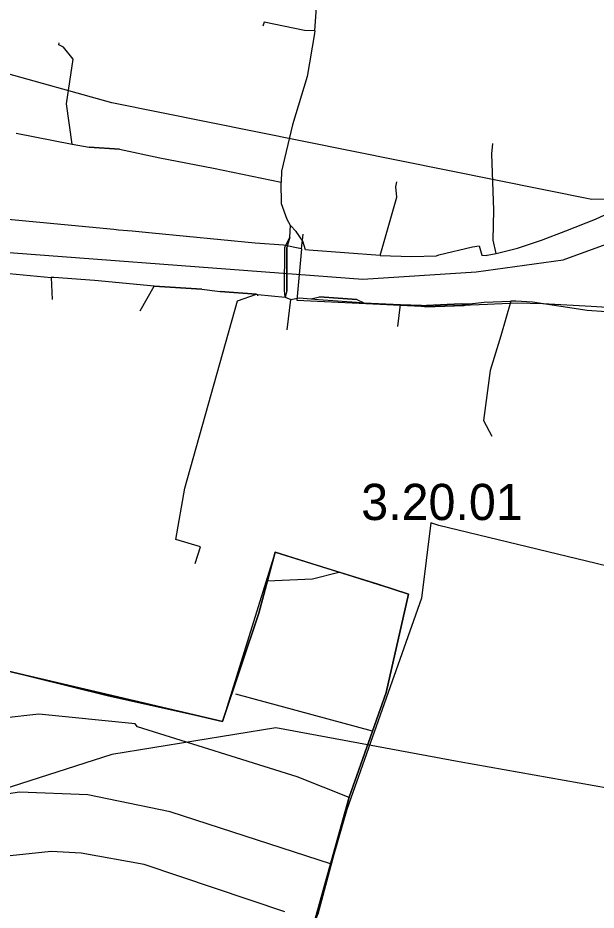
# Model space of a CAD drawing. Extents: x -662500 to -653478, y -1056827 to -1049993.
# Drawn here: x -660470.9 to -660351.1, y -1052282.8 to -1052097.9 of the extents above; entities that cross this region are included whole.
import ezdxf

# ---------------------------------------------------------------- set-up
doc = ezdxf.new("R2010")
doc.units = 0
for name, color, linetype in [('Vrstva 1', 7, 'Continuous'), ('Vrstva 20', 7, 'Continuous'), ('Vrstva 24', 7, 'Continuous'), ('Vrstva 45', 7, 'Continuous'), ('Vrstva 48', 7, 'Continuous'), ('Vrstva 5', 7, 'Continuous'), ('Vrstva 6', 7, 'Continuous'), ('Vrstva 7', 7, 'Continuous')]:
    doc.layers.add(name, color=color, linetype=linetype)

msp = doc.modelspace()

# ---------------------------------------------------------------- linework, layer by layer
at = {"layer": 'Vrstva 1'}
msp.add_lwpolyline([(-660408.77, -1052283.62), (-660402.29, -1052259.33), (-660394.65, -1052237.63), (-660389.99, -1052217.3), (-660396.18, -1052215.3), (-660414.84, -1052209.49), (-660417.67, -1052208.59), (-660421.03, -1052221.2), (-660427.21, -1052239.6), (-660428.58, -1052243.68), (-660452.47, -1052238.38), (-660475.36, -1052232.69), (-660497.36, -1052226.43)], dxfattribs=at)
at = {"layer": 'Vrstva 20'}
msp.add_lwpolyline([(-660611.17, -1052274.32), (-660487.99, -1052312.15), (-660486.82, -1052314.01), (-660462.36, -1052329.02), (-660459.17, -1052336.8), (-660433.93, -1052352.12), (-660408.77, -1052283.62), (-660402.29, -1052259.33), (-660394.65, -1052237.63), (-660389.99, -1052217.3), (-660417.67, -1052208.59), (-660428.58, -1052243.68), (-660475.36, -1052232.69), (-660499.48, -1052225.45), (-660495.07, -1052211.29), (-660578.14, -1052190.03), (-660563.85, -1052144.19), (-660586.5, -1052144.05), (-660704.06, -1052109.9), (-660743.35, -1052235.04)], close=True, dxfattribs=at)
at = {"layer": 'Vrstva 24'}
for points in [[(-660328, -1052135), (-660352, -1052135.5), (-660451.5, -1052115.5), (-660661, -1052057), (-660695, -1052042.5), (-660723, -1052024.5), (-660747.5, -1052000), (-660756.5, -1051991), (-660777.56, -1051972.71)], [(-660320.5, -1052262.5), (-660379.5, -1052252), (-660417.5, -1052245), (-660451.5, -1052250.5), (-660478, -1052259), (-660504, -1052263), (-660539, -1052261), (-660579, -1052252), (-660609, -1052240.5), (-660650.5, -1052213), (-660664.5, -1052194.5), (-660663.5, -1052181.5), (-660652.5, -1052172), (-660629.5, -1052164.5), (-660535, -1052163), (-660529, -1052158), (-660526, -1052149), (-660537.5, -1052137), (-660493, -1052145), (-660399.5, -1052152), (-660376, -1052150.5), (-660358, -1052148), (-660341.5, -1052142)]]:
    msp.add_lwpolyline(points, dxfattribs=at)
at = {"layer": 'Vrstva 45'}
for p, q in [((-660409.45, -1052100.6), (-660408.7, -1052090.8)), ((-660409.45, -1052100.6), (-660408.7, -1052090.8)), ((-660409.45, -1052100.6), (-660408.7, -1052090.8)), ((-660409.45, -1052100.6), (-660408.7, -1052090.8)), ((-660471.3, -1052121.8), (-660459.7, -1052124.03)), ((-660471.3, -1052121.8), (-660459.7, -1052124.03)), ((-660449.9, -1052125.06), (-660456.15, -1052124.67)), ((-660449.9, -1052125.06), (-660456.15, -1052124.67)), ((-660357.45, -1052142.04), (-660351.29, -1052139.56)), ((-660357.45, -1052142.04), (-660351.29, -1052139.56)), ((-660414.61, -1052143.32), (-660414.46, -1052140.93)), ((-660414.61, -1052143.32), (-660414.46, -1052140.93)), ((-660414.61, -1052143.32), (-660414.46, -1052140.93)), ((-660414.61, -1052143.32), (-660414.46, -1052140.93)), ((-660414.46, -1052140.93), (-660413.28, -1052142.15)), ((-660414.46, -1052140.93), (-660413.28, -1052142.15)), ((-660414.46, -1052140.93), (-660413.28, -1052142.15)), ((-660414.46, -1052140.93), (-660413.28, -1052142.15)), ((-660413.28, -1052142.15), (-660413.15, -1052142.16)), ((-660413.28, -1052142.15), (-660413.15, -1052142.16)), ((-660413.28, -1052142.15), (-660413.15, -1052142.16)), ((-660413.28, -1052142.15), (-660413.15, -1052142.16)), ((-660412.15, -1052145.73), (-660411.84, -1052142.72)), ((-660412.15, -1052145.73), (-660411.84, -1052142.72)), ((-660415.67, -1052154.38), (-660415.63, -1052145.48)), ((-660415.67, -1052154.38), (-660415.63, -1052145.48)), ((-660415.23, -1052154.43), (-660415.22, -1052145.47)), ((-660415.23, -1052154.43), (-660415.22, -1052145.47)), ((-660383.74, -1052147.01), (-660376.78, -1052145.3)), ((-660383.74, -1052147.01), (-660376.78, -1052145.3)), ((-660395.86, -1052147.1), (-660389.4, -1052147.3)), ((-660395.86, -1052147.1), (-660389.4, -1052147.3)), ((-660464.01, -1052151.68), (-660463.81, -1052156.27)), ((-660464.01, -1052151.68), (-660463.81, -1052156.27)), ((-660455.08, -1052152.33), (-660463.52, -1052151.69)), ((-660455.08, -1052152.33), (-660463.52, -1052151.69)), ((-660445.59, -1052158.59), (-660442.67, -1052153.44)), ((-660445.59, -1052158.59), (-660442.67, -1052153.44)), ((-660432.84, -1052154.12), (-660442.67, -1052153.44)), ((-660432.84, -1052154.12), (-660442.67, -1052153.44)), ((-660421.53, -1052155.16), (-660429.05, -1052154.56)), ((-660421.53, -1052155.16), (-660429.05, -1052154.56)), ((-660421.53, -1052155.16), (-660421.22, -1052155.19)), ((-660421.53, -1052155.16), (-660421.22, -1052155.19)), ((-660421.24, -1052155.49), (-660421.22, -1052155.19)), ((-660421.24, -1052155.49), (-660421.22, -1052155.19)), ((-660421.22, -1052155.19), (-660415.55, -1052155.73)), ((-660421.22, -1052155.19), (-660415.55, -1052155.73)), ((-660415.55, -1052155.73), (-660414.38, -1052156.21)), ((-660415.55, -1052155.73), (-660414.38, -1052156.21)), ((-660415.55, -1052155.73), (-660414.38, -1052156.21)), ((-660415.55, -1052155.73), (-660414.38, -1052156.21)), ((-660415.16, -1052162.49), (-660414.38, -1052156.21)), ((-660415.16, -1052162.49), (-660414.38, -1052156.21)), ((-660408.67, -1052156.23), (-660400.79, -1052156.82)), ((-660408.67, -1052156.23), (-660400.79, -1052156.82)), ((-660400.73, -1052156.27), (-660408.48, -1052155.7)), ((-660400.73, -1052156.27), (-660408.48, -1052155.7)), ((-660399.25, -1052156.91), (-660391.69, -1052157.24)), ((-660399.25, -1052156.91), (-660391.69, -1052157.24)), ((-660399.25, -1052156.91), (-660391.69, -1052157.24)), ((-660399.25, -1052156.91), (-660391.69, -1052157.24)), ((-660392.21, -1052161.8), (-660391.69, -1052157.24)), ((-660392.21, -1052161.8), (-660391.69, -1052157.24)), ((-660391.69, -1052157.24), (-660387.41, -1052157.44)), ((-660391.69, -1052157.24), (-660387.41, -1052157.44)), ((-660391.69, -1052157.24), (-660387.41, -1052157.44)), ((-660391.69, -1052157.24), (-660387.41, -1052157.44)), ((-660378.45, -1052157.45), (-660386.48, -1052157.76)), ((-660378.45, -1052157.45), (-660386.48, -1052157.76)), ((-660379.12, -1052157.16), (-660386.3, -1052157.46)), ((-660379.12, -1052157.16), (-660386.3, -1052157.46)), ((-660362.2, -1052157.04), (-660352.16, -1052157.62)), ((-660362.2, -1052157.04), (-660352.16, -1052157.62))]:
    msp.add_line(p, q, dxfattribs=at)
for points in [[(-660409.45, -1052100.6), (-660411.57, -1052100.48), (-660419.94, -1052098.78), (-660420.18, -1052099.59)], [(-660409.45, -1052100.6), (-660411.57, -1052100.48), (-660419.94, -1052098.78), (-660420.18, -1052099.59)], [(-660409.45, -1052100.6), (-660409.46, -1052101.13), (-660410.98, -1052110.03), (-660414.04, -1052120.04), (-660416.32, -1052129.63), (-660416.38, -1052131.95)], [(-660409.45, -1052100.6), (-660409.46, -1052101.13), (-660410.98, -1052110.03), (-660414.04, -1052120.04), (-660416.32, -1052129.63), (-660416.38, -1052131.95)], [(-660409.45, -1052100.6), (-660409.46, -1052101.13), (-660410.98, -1052110.03), (-660414.04, -1052120.04), (-660416.32, -1052129.63), (-660416.38, -1052131.95)], [(-660409.45, -1052100.6), (-660409.46, -1052101.13), (-660410.98, -1052110.03), (-660414.04, -1052120.04), (-660416.32, -1052129.63), (-660416.38, -1052131.95)], [(-660459.7, -1052124.03), (-660460.85, -1052115.69), (-660459.5, -1052106.42), (-660461.49, -1052103.98), (-660462.47, -1052103.46), (-660462.39, -1052103.03)], [(-660459.7, -1052124.03), (-660460.85, -1052115.69), (-660459.5, -1052106.42), (-660461.49, -1052103.98), (-660462.47, -1052103.46), (-660462.39, -1052103.03)], [(-660459.7, -1052124.03), (-660456.15, -1052124.67), (-660449.9, -1052125.06), (-660441.55, -1052126.88), (-660430.39, -1052129.05), (-660416.38, -1052131.95)], [(-660459.7, -1052124.03), (-660456.15, -1052124.67), (-660449.9, -1052125.06), (-660441.55, -1052126.88), (-660430.39, -1052129.05), (-660416.38, -1052131.95)], [(-660371.84, -1052146.69), (-660372.47, -1052143.93), (-660372.32, -1052137.7), (-660372.73, -1052126.06), (-660372.52, -1052123.9)], [(-660371.84, -1052146.69), (-660372.47, -1052143.93), (-660372.32, -1052137.7), (-660372.73, -1052126.06), (-660372.52, -1052123.9)], [(-660414.46, -1052140.93), (-660415.17, -1052139.69), (-660416.3, -1052136.39), (-660416.38, -1052131.95)], [(-660414.46, -1052140.93), (-660415.17, -1052139.69), (-660416.3, -1052136.39), (-660416.38, -1052131.95)], [(-660414.46, -1052140.93), (-660415.17, -1052139.69), (-660416.3, -1052136.39), (-660416.38, -1052131.95)], [(-660414.46, -1052140.93), (-660415.17, -1052139.69), (-660416.3, -1052136.39), (-660416.38, -1052131.95)], [(-660395.86, -1052147.1), (-660392.4, -1052135.02), (-660392.66, -1052132.92), (-660392.41, -1052131.85)], [(-660395.86, -1052147.1), (-660392.4, -1052135.02), (-660392.66, -1052132.92), (-660392.41, -1052131.85)], [(-660371.84, -1052146.69), (-660367.41, -1052145.57), (-660362.45, -1052143.97), (-660357.45, -1052142.04), (-660351.29, -1052139.56), (-660343.57, -1052136.03), (-660337.69, -1052133.38)], [(-660371.84, -1052146.69), (-660367.41, -1052145.57), (-660362.45, -1052143.97), (-660357.45, -1052142.04), (-660351.29, -1052139.56), (-660343.57, -1052136.03), (-660337.69, -1052133.38)], [(-660450.08, -1052141.84), (-660451.03, -1052141.75), (-660516.13, -1052135.6)], [(-660450.08, -1052141.84), (-660451.03, -1052141.75), (-660516.13, -1052135.6)], [(-660443.11, -1052142.49), (-660447.25, -1052142.1), (-660450.08, -1052141.84)], [(-660443.11, -1052142.49), (-660447.25, -1052142.1), (-660450.08, -1052141.84)], [(-660412.15, -1052145.73), (-660415.93, -1052144.97), (-660421.76, -1052144.56), (-660443.11, -1052142.49)], [(-660412.15, -1052145.73), (-660415.93, -1052144.97), (-660421.76, -1052144.56), (-660443.11, -1052142.49)], [(-660415.55, -1052155.73), (-660415.67, -1052154.38), (-660415.63, -1052145.48), (-660414.61, -1052143.32)], [(-660415.55, -1052155.73), (-660415.67, -1052154.38), (-660415.63, -1052145.48), (-660414.61, -1052143.32)], [(-660414.61, -1052143.32), (-660415.22, -1052145.47), (-660415.23, -1052154.43), (-660415.55, -1052155.73)], [(-660414.61, -1052143.32), (-660415.22, -1052145.47), (-660415.23, -1052154.43), (-660415.55, -1052155.73)], [(-660395.86, -1052147.1), (-660410.66, -1052146.01), (-660411.32, -1052145.93), (-660411.9, -1052144.14), (-660413.28, -1052142.15)], [(-660395.86, -1052147.1), (-660410.66, -1052146.01), (-660411.32, -1052145.93), (-660411.9, -1052144.14), (-660413.28, -1052142.15)], [(-660395.86, -1052147.1), (-660389.4, -1052147.3), (-660384.24, -1052147.22), (-660383.74, -1052147.01), (-660376.78, -1052145.3), (-660375.37, -1052145.15), (-660374.79, -1052147.04), (-660373.91, -1052147.12), (-660373.75, -1052147.05), (-660371.84, -1052146.69)], [(-660395.86, -1052147.1), (-660389.4, -1052147.3), (-660384.24, -1052147.22), (-660383.74, -1052147.01), (-660376.78, -1052145.3), (-660375.37, -1052145.15), (-660374.79, -1052147.04), (-660373.91, -1052147.12), (-660373.75, -1052147.05), (-660371.84, -1052146.69)], [(-660412.15, -1052145.73), (-660413.13, -1052156.36), (-660385.96, -1052157.72), (-660373.68, -1052157.19), (-660372.23, -1052157.15)], [(-660412.15, -1052145.73), (-660413.13, -1052156.36), (-660385.96, -1052157.72), (-660373.68, -1052157.19), (-660372.23, -1052157.15)], [(-660492.67, -1052149.21), (-660484.44, -1052149.72), (-660464.01, -1052151.68)], [(-660492.67, -1052149.21), (-660484.44, -1052149.72), (-660464.01, -1052151.68)], [(-660442.67, -1052153.44), (-660455.08, -1052152.33), (-660463.52, -1052151.69), (-660464.01, -1052151.68)], [(-660442.67, -1052153.44), (-660455.08, -1052152.33), (-660463.52, -1052151.69), (-660464.01, -1052151.68)], [(-660442.67, -1052153.44), (-660432.84, -1052154.12), (-660429.05, -1052154.56), (-660421.53, -1052155.16)], [(-660442.67, -1052153.44), (-660432.84, -1052154.12), (-660429.05, -1052154.56), (-660421.53, -1052155.16)], [(-660434.19, -1052210.92), (-660433.11, -1052207.46), (-660438.23, -1052205.95), (-660436.37, -1052195.34), (-660425.46, -1052156.53), (-660421.53, -1052155.16)], [(-660434.19, -1052210.92), (-660433.11, -1052207.46), (-660438.23, -1052205.95), (-660436.37, -1052195.34), (-660425.46, -1052156.53), (-660421.53, -1052155.16)], [(-660414.38, -1052156.21), (-660412.65, -1052155.91), (-660410.2, -1052156.13)], [(-660414.38, -1052156.21), (-660412.65, -1052155.91), (-660410.2, -1052156.13)], [(-660414.38, -1052156.21), (-660412.65, -1052155.91), (-660410.2, -1052156.13)], [(-660414.38, -1052156.21), (-660412.65, -1052155.91), (-660410.2, -1052156.13)], [(-660410.2, -1052156.13), (-660408.48, -1052155.7), (-660400.73, -1052156.27), (-660399.25, -1052156.91)], [(-660410.2, -1052156.13), (-660408.48, -1052155.7), (-660400.73, -1052156.27), (-660399.25, -1052156.91)], [(-660410.2, -1052156.13), (-660408.67, -1052156.23), (-660400.79, -1052156.82), (-660399.25, -1052156.91)], [(-660410.2, -1052156.13), (-660408.67, -1052156.23), (-660400.79, -1052156.82), (-660399.25, -1052156.91)], [(-660377.38, -1052157.14), (-660374.33, -1052156.77), (-660368.83, -1052156.61)], [(-660377.38, -1052157.14), (-660374.33, -1052156.77), (-660368.83, -1052156.61)], [(-660377.38, -1052157.14), (-660374.33, -1052156.77), (-660368.83, -1052156.61)], [(-660377.38, -1052157.14), (-660374.33, -1052156.77), (-660368.83, -1052156.61)], [(-660368.83, -1052156.61), (-660370.91, -1052163.74), (-660373.07, -1052170.94), (-660374.45, -1052181.29), (-660372.76, -1052184.55)], [(-660368.83, -1052156.61), (-660370.91, -1052163.74), (-660373.07, -1052170.94), (-660374.45, -1052181.29), (-660372.76, -1052184.55)], [(-660349.05, -1052158.82), (-660352.99, -1052158.54), (-660364.35, -1052156.82), (-660367.76, -1052156.58), (-660368.83, -1052156.61)], [(-660349.05, -1052158.82), (-660352.99, -1052158.54), (-660364.35, -1052156.82), (-660367.76, -1052156.58), (-660368.83, -1052156.61)], [(-660349.05, -1052158.82), (-660352.99, -1052158.54), (-660364.35, -1052156.82), (-660367.76, -1052156.58), (-660368.83, -1052156.61)], [(-660349.05, -1052158.82), (-660352.99, -1052158.54), (-660364.35, -1052156.82), (-660367.76, -1052156.58), (-660368.83, -1052156.61)], [(-660387.41, -1052157.44), (-660386.48, -1052157.76), (-660378.45, -1052157.45), (-660377.38, -1052157.14)], [(-660387.41, -1052157.44), (-660386.3, -1052157.46), (-660379.12, -1052157.16), (-660377.38, -1052157.14)], [(-660387.41, -1052157.44), (-660386.48, -1052157.76), (-660378.45, -1052157.45), (-660377.38, -1052157.14)], [(-660387.41, -1052157.44), (-660386.3, -1052157.46), (-660379.12, -1052157.16), (-660377.38, -1052157.14)], [(-660372.23, -1052157.15), (-660367.47, -1052156.91), (-660362.2, -1052157.04)], [(-660372.23, -1052157.15), (-660367.47, -1052156.91), (-660362.2, -1052157.04)], [(-660352.16, -1052157.62), (-660335.69, -1052158.64), (-660326.78, -1052158.82)], [(-660352.16, -1052157.62), (-660335.69, -1052158.64), (-660326.78, -1052158.82)]]:
    msp.add_lwpolyline(points, dxfattribs=at)
at = {"layer": 'Vrstva 48'}
msp.add_lwpolyline([(-660129.33, -1052258.85), (-660178.23, -1052230.25), (-660235.74, -1052210.41), (-660323.75, -1052188.77), (-660330.58, -1052215.92), (-660383.74, -1052203.08), (-660385.39, -1052202.51), (-660387.33, -1052218.12), (-660402.76, -1052261.89), (-660409.6, -1052285.62)], dxfattribs=at)
at = {"layer": 'Vrstva 5'}
msp.add_lwpolyline([(-660757.57, -1052084.94), (-660618.97, -1052129.25), (-660588.97, -1052137.76), (-660563.85, -1052144.19), (-660578.14, -1052190.03), (-660527.17, -1052203.32), (-660495.07, -1052211.29), (-660499.48, -1052225.45), (-660497.36, -1052226.43), (-660475.36, -1052232.69), (-660428.58, -1052243.68), (-660421.03, -1052221.2), (-660417.67, -1052208.59), (-660396.18, -1052215.3), (-660389.99, -1052217.3), (-660394.65, -1052237.63), (-660402.29, -1052259.33), (-660408.77, -1052283.62)], dxfattribs=at)
at = {"layer": 'Vrstva 6'}
msp.add_lwpolyline([(-660462.36, -1052329.02), (-660459.17, -1052336.8), (-660433.93, -1052352.12), (-660409.6, -1052285.62), (-660402.29, -1052259.33), (-660394.65, -1052237.63), (-660389.99, -1052217.3), (-660417.67, -1052208.59), (-660421.03, -1052221.2), (-660428.58, -1052243.68), (-660452.47, -1052238.38), (-660475.36, -1052232.69), (-660499.48, -1052225.45), (-660495.07, -1052211.29), (-660578.14, -1052190.03), (-660563.85, -1052144.19), (-660586.5, -1052144.05), (-660704.06, -1052109.9), (-660743.35, -1052235.04), (-661096.01, -1052128.52), (-661110.22, -1052170.21), (-660506.09, -1052352.23), (-660487.99, -1052312.15)], close=True, dxfattribs=at)
at = {"layer": 'Vrstva 7'}
for p, q in [((-660409.93, -1052214.09), (-660404.46, -1052212.72)), ((-660419.26, -1052214.55), (-660409.93, -1052214.09)), ((-660397.48, -1052245.66), (-660425.8, -1052238.04)), ((-660466.62, -1052242.15), (-660473.99, -1052243)), ((-660446.63, -1052244.13), (-660466.62, -1052242.15)), ((-660446.14, -1052244.77), (-660446.63, -1052244.13)), ((-660413.05, -1052255.11), (-660446.14, -1052244.77)), ((-660402.31, -1052259.4), (-660413.05, -1052255.11)), ((-660470.58, -1052258.3), (-660485.89, -1052260.57)), ((-660456.41, -1052258.87), (-660470.58, -1052258.3)), ((-660439.41, -1052262.41), (-660456.41, -1052258.87)), ((-660406, -1052273.22), (-660439.41, -1052262.41)), ((-660464.07, -1052270.63), (-660475.4, -1052271.77)), ((-660457.83, -1052270.92), (-660464.07, -1052270.63)), ((-660444.79, -1052273.32), (-660457.83, -1052270.92)), ((-660415.6, -1052283.1), (-660444.79, -1052273.32))]:
    msp.add_line(p, q, dxfattribs=at)

# ---------------------------------------------------------------- texts
at = {"layer": 'Vrstva 24'}
msp.add_text('3.20.01', height=7.5, dxfattribs=at).set_placement((-660399.81, -1052201.93))

doc.saveas('drawing.dxf')
